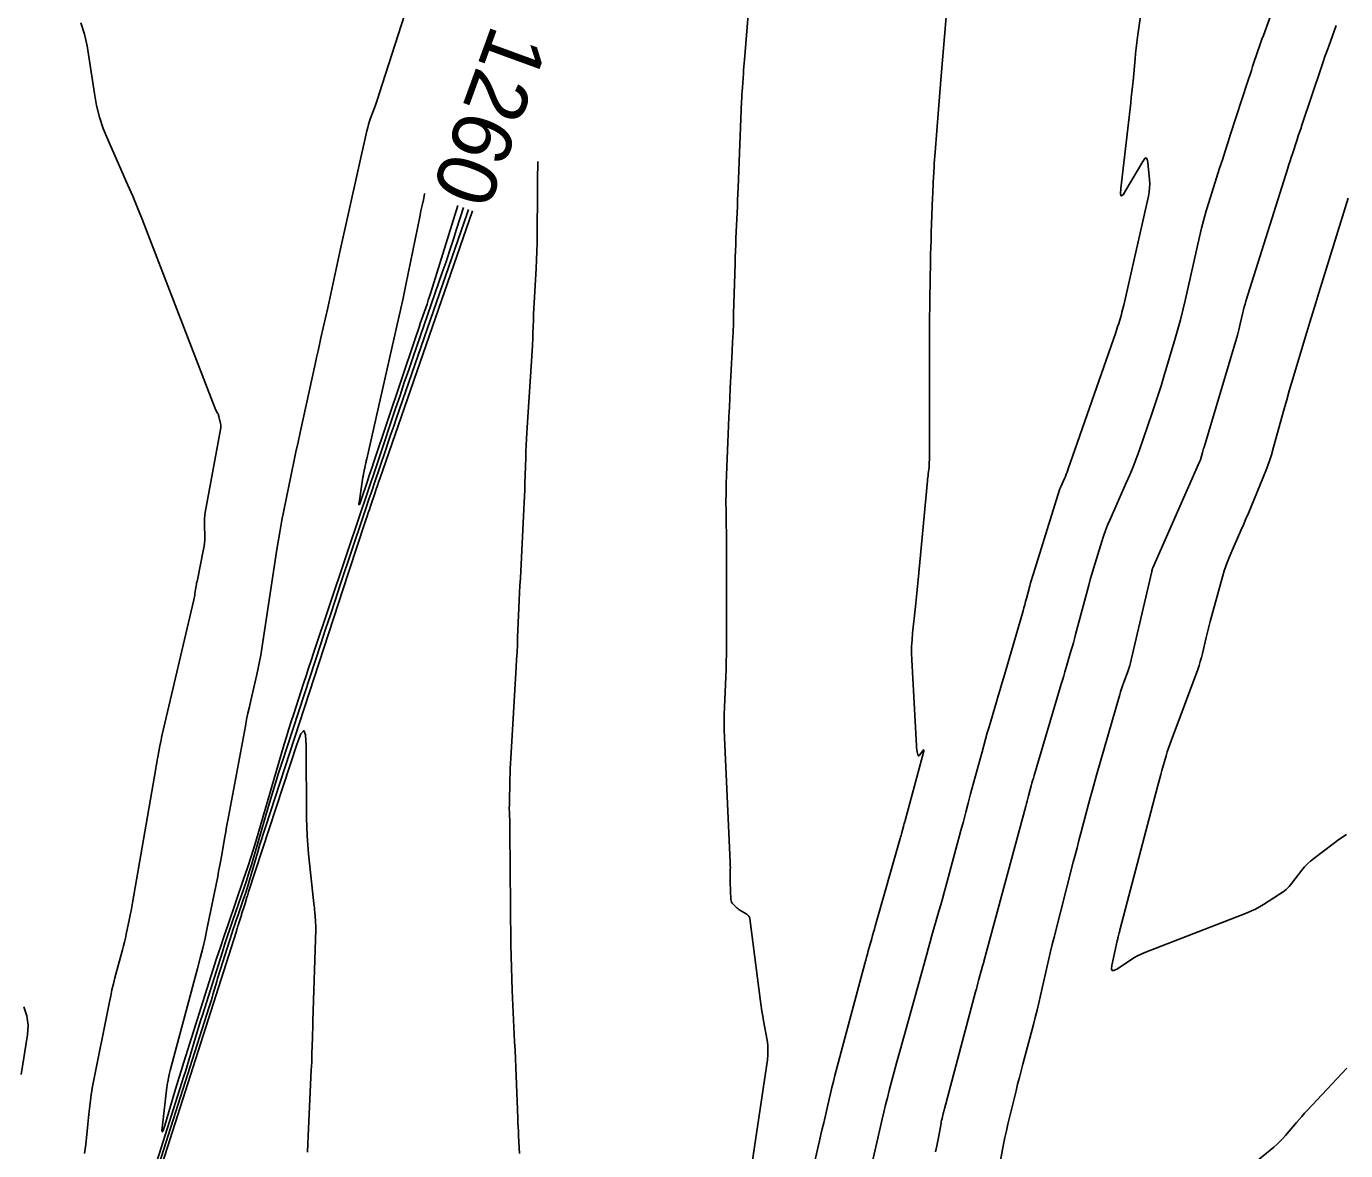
# Model space of a CAD drawing. Extents: x 658976 to 668726, y 639543 to 647196.
# Drawn here: x 661560 to 661691.9, y 641134.6 to 641247 of the extents above; entities that cross this region are included whole.
import ezdxf

# ---------------------------------------------------------------- set-up
doc = ezdxf.new("R2010")
doc.units = 0
for name, color, linetype in [('Ex_Contour Labels', 7, 'Continuous'), ('Ex_Major Contours', 7, 'Continuous'), ('Ex_Minor Contours', 7, 'Continuous')]:
    doc.layers.add(name, color=color, linetype=linetype)

msp = doc.modelspace()

# ---------------------------------------------------------------- linework, layer by layer
at = {"layer": 'Ex_Major Contours'}
for points in [[(661672.25, 641254.14), (661671.08, 641245.9), (661671, 641245.35), (661670.93, 641244.8), (661670.87, 641244.25), (661670.82, 641243.71), (661670.62, 641241.51), (661670.57, 641240.96), (661670.51, 641240.41), (661670.45, 641239.86), (661670.39, 641239.32), (661669.39, 641230.77), (661669.36, 641230.24), (661669.44, 641230.03), (661669.63, 641230.15), (661669.92, 641230.59), (661671.6, 641233.48), (661671.79, 641233.75), (661671.94, 641233.82), (661672.05, 641233.69), (661672.11, 641233.37), (661672.27, 641231.67), (661672.29, 641231.25), (661672.28, 641230.83), (661672.23, 641230.41), (661672.16, 641230), (661669.69, 641219.1), (661669.64, 641218.87), (661669.58, 641218.64), (661669.52, 641218.41), (661669.46, 641218.18), (661669.19, 641217.28), (661669.12, 641217.05), (661669.05, 641216.83), (661668.97, 641216.6), (661668.9, 641216.38), (661664.1, 641202.64), (661664.03, 641202.42), (661663.95, 641202.21), (661663.86, 641202), (661663.77, 641201.8), (661663.41, 641200.97), (661663.32, 641200.76), (661663.23, 641200.55), (661663.16, 641200.34), (661663.09, 641200.12), (661660.67, 641192.29), (661660.57, 641191.98), (661660.48, 641191.67), (661660.39, 641191.36), (661660.31, 641191.05), (661659.98, 641189.8), (661659.89, 641189.49), (661659.81, 641189.18), (661659.72, 641188.87), (661659.63, 641188.56), (661657.7, 641181.94), (661657.52, 641181.32), (661657.33, 641180.7), (661657.15, 641180.08), (661656.97, 641179.46), (661656.23, 641176.98), (661656.05, 641176.36), (661655.87, 641175.74), (661655.7, 641175.12), (661655.53, 641174.49), (661654.39, 641170.27), (661654.15, 641169.35), (661653.9, 641168.44), (661653.66, 641167.53), (661653.41, 641166.62), (661651.9, 641161.03), (661651.74, 641160.41), (661651.57, 641159.8), (661651.4, 641159.18), (661651.22, 641158.57), (661650.52, 641156.11), (661650.35, 641155.5), (661650.17, 641154.88), (661650, 641154.27), (661649.83, 641153.65), (661647.8, 641146.34), (661647.6, 641145.63), (661647.41, 641144.91), (661647.21, 641144.2), (661647.02, 641143.49), (661646.26, 641140.63), (661646.07, 641139.91), (661645.89, 641139.2), (661645.71, 641138.48), (661645.55, 641137.76), (661642.97, 641126.54)], [(661599.83, 641230.27), (661599.81, 641230.21), (661599.69, 641229.64), (661599.56, 641229.08), (661599.44, 641228.52), (661599.33, 641227.95), (661597.92, 641221.14), (661597.65, 641219.82), (661597.36, 641218.49), (661597.07, 641217.17), (661596.78, 641215.86), (661594.03, 641203.75), (661594, 641203.65), (661593.98, 641203.55), (661593.96, 641203.44), (661593.94, 641203.34), (661593.84, 641202.88), (661593.82, 641202.8), (661593.8, 641202.72), (661593.78, 641202.64), (661593.77, 641202.56), (661593.7, 641202.24), (661593.69, 641202.17), (661593.67, 641202.09), (661593.66, 641202.01), (661593.64, 641201.92), (661593.29, 641199.59), (661593.25, 641199.27), (661593.26, 641199.16), (661593.32, 641199.26), (661593.43, 641199.55), (661594.09, 641201.52), (661594.25, 641201.99), (661594.4, 641202.45), (661594.56, 641202.91), (661594.71, 641203.37), (661598.86, 641215.75), (661598.99, 641216.13), (661599.12, 641216.52), (661599.25, 641216.91), (661599.38, 641217.29), (661599.92, 641218.83), (661600.05, 641219.22), (661600.18, 641219.6), (661600.3, 641219.99), (661600.43, 641220.38), (661603.14, 641229.07)]]:
    msp.add_lwpolyline(points, dxfattribs=at)
at = {"layer": 'Ex_Minor Contours'}
for points in [[(661600.69, 641257.11), (661595.27, 641240.22), (661595.17, 641239.91), (661595.06, 641239.61), (661594.96, 641239.3), (661594.85, 641239), (661594.41, 641237.78), (661594.31, 641237.48), (661594.21, 641237.17), (661594.13, 641236.86), (661594.05, 641236.54), (661591.32, 641224.43), (661591.22, 641223.97), (661591.12, 641223.5), (661591.02, 641223.04), (661590.92, 641222.57), (661590.54, 641220.71), (661590.44, 641220.25), (661590.34, 641219.78), (661590.24, 641219.32), (661590.14, 641218.86), (661589.45, 641215.84), (661589.3, 641215.19), (661589.16, 641214.53), (661589.01, 641213.87), (661588.87, 641213.21), (661587.37, 641206.38), (661587.16, 641205.41), (661586.95, 641204.44), (661586.75, 641203.46), (661586.54, 641202.49), (661585.74, 641198.59), (661585.54, 641197.62), (661585.36, 641196.64), (661585.19, 641195.66), (661585.03, 641194.68), (661583.54, 641184.79), (661583.43, 641184.13), (661583.31, 641183.49), (661583.18, 641182.84), (661583.04, 641182.19), (661582.44, 641179.62), (661582.29, 641178.98), (661582.15, 641178.33), (661582.02, 641177.69), (661581.89, 641177.04), (661580.2, 641167.97), (661580.11, 641167.48), (661580.02, 641166.98), (661579.93, 641166.48), (661579.84, 641165.99), (661579.5, 641164), (661579.41, 641163.5), (661579.32, 641163), (661579.22, 641162.51), (661579.13, 641162.01), (661578.07, 641156.89), (661577.86, 641155.87), (661577.63, 641154.86), (661577.38, 641153.85), (661577.12, 641152.84), (661574.37, 641142.63), (661574.34, 641142.5), (661574.3, 641142.36), (661574.27, 641142.22), (661574.24, 641142.08), (661574.13, 641141.51), (661574.1, 641141.37), (661574.08, 641141.23), (661574.06, 641141.09), (661574.04, 641140.95), (661573.6, 641137.18), (661573.55, 641136.67), (661573.58, 641136.5), (661573.67, 641136.65), (661573.83, 641137.13), (661574.81, 641140.42), (661575.04, 641141.19), (661575.27, 641141.95), (661575.51, 641142.71), (661575.74, 641143.47), (661578.65, 641152.67), (661579.02, 641153.81), (661579.39, 641154.95), (661579.77, 641156.09), (661580.16, 641157.22), (661581.72, 641161.76), (661582.11, 641162.89), (661582.48, 641164.03), (661582.83, 641165.18), (661583.18, 641166.33), (661585.78, 641175.23), (661586.01, 641175.99), (661586.24, 641176.76), (661586.48, 641177.52), (661586.72, 641178.28), (661587.71, 641181.31), (661587.96, 641182.07), (661588.21, 641182.83), (661588.46, 641183.59), (661588.71, 641184.34), (661593.47, 641198.51), (661593.9, 641199.8), (661594.33, 641201.08), (661594.76, 641202.37), (661595.19, 641203.65), (661596.91, 641208.8), (661597.35, 641210.09), (661597.78, 641211.37), (661598.22, 641212.65), (661598.66, 641213.94), (661601.58, 641222.36), (661601.95, 641223.44), (661602.31, 641224.52), (661602.66, 641225.6), (661603, 641226.69), (661603.68, 641228.87)], [(661631.92, 641129.22), (661634.07, 641143.7), (661634.12, 641144.19), (661634.13, 641144.68), (661634.11, 641145.16), (661634.04, 641145.65), (661633.69, 641147.59), (661633.61, 641148.07), (661633.53, 641148.56), (661633.46, 641149.05), (661633.39, 641149.53), (661632.31, 641157.82), (661632.28, 641157.95), (661632.22, 641158.07), (661632.13, 641158.17), (661632.02, 641158.25), (661631.49, 641158.54), (661631.37, 641158.61), (661631.26, 641158.69), (661631.15, 641158.78), (661631.05, 641158.87), (661630.64, 641159.25), (661630.55, 641159.35), (661630.48, 641159.46), (661630.44, 641159.58), (661630.43, 641159.71), (661630.35, 641161.44), (661630.35, 641161.6), (661630.34, 641161.77), (661630.34, 641161.93), (661630.35, 641162.09), (661630.36, 641162.75), (661630.37, 641162.92), (661630.36, 641163.08), (661630.36, 641163.24), (661630.36, 641163.41), (661629.79, 641175.92), (661629.76, 641176.68), (661629.75, 641177.43), (661629.76, 641178.19), (661629.78, 641178.94), (661629.91, 641181.96), (661629.94, 641182.71), (661629.96, 641183.46), (661629.97, 641184.22), (661629.98, 641184.97), (661630, 641191.38), (661630, 641192.27), (661630, 641193.17), (661629.99, 641194.06), (661629.98, 641194.96), (661629.94, 641198.55), (661629.93, 641199.44), (661629.94, 641200.34), (661629.96, 641201.24), (661629.99, 641202.13), (661630.19, 641207.05), (661630.23, 641207.99), (661630.27, 641208.92), (661630.31, 641209.85), (661630.36, 641210.78), (661630.55, 641214.51), (661630.6, 641215.44), (661630.64, 641216.38), (661630.68, 641217.31), (661630.7, 641218.24), (661630.84, 641223.28), (661630.86, 641223.91), (661630.88, 641224.55), (661630.91, 641225.18), (661630.93, 641225.81), (661631.04, 641228.34), (661631.07, 641228.97), (661631.1, 641229.6), (661631.13, 641230.23), (661631.15, 641230.86), (661631.49, 641239.47), (661631.51, 641239.82), (661631.52, 641240.16), (661631.54, 641240.51), (661631.57, 641240.86), (661631.67, 641242.25), (661631.69, 641242.6), (661631.72, 641242.95), (661631.75, 641243.29), (661631.77, 641243.64), (661632.59, 641253.44)], [(661686.44, 641253.78), (661683.65, 641246.06), (661683.51, 641245.68), (661683.38, 641245.29), (661683.24, 641244.9), (661683.11, 641244.51), (661682.58, 641242.95), (661682.45, 641242.56), (661682.32, 641242.17), (661682.19, 641241.78), (661682.07, 641241.38), (661680.37, 641236.19), (661680.09, 641235.34), (661679.82, 641234.49), (661679.55, 641233.64), (661679.28, 641232.79), (661678.2, 641229.38), (661677.94, 641228.52), (661677.7, 641227.66), (661677.48, 641226.8), (661677.27, 641225.93), (661675.83, 641219.56), (661675.61, 641218.61), (661675.37, 641217.66), (661675.11, 641216.71), (661674.84, 641215.77), (661673.71, 641211.97), (661673.44, 641211.06), (661673.15, 641210.15), (661672.85, 641209.24), (661672.54, 641208.34), (661671.23, 641204.56), (661670.93, 641203.75), (661670.62, 641202.94), (661670.3, 641202.14), (661669.95, 641201.34), (661668.3, 641197.63), (661668.08, 641197.11), (661667.87, 641196.58), (661667.68, 641196.04), (661667.51, 641195.5), (661666.83, 641193.32), (661666.67, 641192.78), (661666.51, 641192.23), (661666.35, 641191.69), (661666.2, 641191.14), (661664.88, 641186.19), (661664.77, 641185.78), (661664.66, 641185.36), (661664.54, 641184.95), (661664.42, 641184.54), (661663.94, 641182.89), (661663.82, 641182.48), (661663.7, 641182.06), (661663.58, 641181.65), (661663.45, 641181.24), (661660.73, 641172.1), (661660.66, 641171.84), (661660.59, 641171.59), (661660.52, 641171.34), (661660.45, 641171.08), (661660.18, 641170.07), (661660.11, 641169.81), (661660.04, 641169.56), (661659.97, 641169.3), (661659.9, 641169.05), (661655.72, 641153.53), (661655.72, 641153.51), (661655.71, 641153.49), (661655.7, 641153.47), (661655.7, 641153.45), (661655.67, 641153.36), (661655.66, 641153.32), (661655.65, 641153.28), (661655.19, 641151.63), (661655.12, 641151.35), (661655.04, 641151.07), (661654.96, 641150.79), (661654.89, 641150.5), (661651.77, 641138.8), (661651.74, 641138.68), (661651.71, 641138.57), (661651.68, 641138.45), (661651.65, 641138.33), (661651.54, 641137.85), (661651.51, 641137.74), (661651.48, 641137.62), (661651.46, 641137.5), (661651.43, 641137.38), (661651.13, 641135.74), (661651.07, 641135.43), (661651.01, 641135.12), (661650.95, 641134.81), (661650.89, 641134.5)], [(661565.82, 641134.34), (661565.88, 641134.79), (661565.93, 641135.24), (661566.14, 641137.26), (661566.18, 641137.59), (661566.21, 641137.92), (661566.25, 641138.25), (661566.29, 641138.58), (661566.44, 641139.9), (661566.48, 641140.23), (661566.53, 641140.56), (661566.59, 641140.88), (661566.65, 641141.21), (661568.3, 641149.48), (661568.43, 641150.08), (661568.56, 641150.68), (661568.71, 641151.29), (661568.86, 641151.88), (661569.62, 641154.7), (661569.72, 641155.09), (661569.82, 641155.47), (661569.91, 641155.86), (661569.99, 641156.25), (661570.31, 641157.81), (661570.39, 641158.2), (661570.46, 641158.59), (661570.53, 641158.98), (661570.6, 641159.37), (661572.93, 641172.81), (661572.98, 641173.09), (661573.03, 641173.38), (661573.08, 641173.66), (661573.14, 641173.94), (661573.35, 641175.08), (661573.4, 641175.36), (661573.46, 641175.64), (661573.52, 641175.92), (661573.58, 641176.2), (661576.74, 641189.68), (661576.77, 641189.83), (661576.8, 641189.98), (661576.83, 641190.14), (661576.85, 641190.29), (661576.95, 641190.9), (661576.97, 641191.05), (661577, 641191.2), (661577.02, 641191.35), (661577.06, 641191.5), (661577.72, 641194.72), (661577.78, 641195.02), (661577.81, 641195.32), (661577.83, 641195.63), (661577.83, 641195.94), (661577.79, 641197.17), (661577.79, 641197.47), (661577.8, 641197.78), (661577.83, 641198.08), (661577.88, 641198.39), (661579.42, 641206.7), (661579.44, 641206.84), (661579.44, 641206.99), (661579.43, 641207.14), (661579.4, 641207.28), (661579.24, 641207.99), (661579.22, 641208.07), (661579.19, 641208.16), (661579.16, 641208.24), (661579.12, 641208.32), (661578.95, 641208.63), (661578.91, 641208.71), (661578.87, 641208.79), (661578.83, 641208.87), (661578.8, 641208.95), (661572.02, 641226.57), (661571.57, 641227.71), (661571.11, 641228.85), (661570.63, 641229.99), (661570.14, 641231.11), (661568.14, 641235.66), (661567.69, 641236.77), (661567.32, 641237.91), (661567.02, 641239.07), (661566.8, 641240.25), (661566.07, 641245.02), (661565.82, 641246.19), (661565.46, 641247.32)], [(661651.94, 641247.93), (661651.46, 641242.03), (661651.39, 641241.19), (661651.32, 641240.35), (661651.26, 641239.51), (661651.19, 641238.67), (661650.84, 641234.39), (661650.81, 641234.02), (661650.78, 641233.64), (661650.76, 641233.27), (661650.74, 641232.89), (661650.65, 641231.39), (661650.63, 641231.01), (661650.62, 641230.64), (661650.6, 641230.26), (661650.58, 641229.88), (661650.45, 641226.33), (661650.43, 641225.62), (661650.41, 641224.9), (661650.39, 641224.18), (661650.38, 641223.47), (661650.32, 641219.7), (661650.3, 641218.84), (661650.29, 641217.97), (661650.29, 641217.1), (661650.29, 641216.24), (661650.27, 641203.63), (661650.26, 641203.45), (661650.26, 641203.28), (661650.24, 641203.1), (661650.23, 641202.93), (661650.15, 641202.24), (661650.13, 641202.06), (661650.11, 641201.89), (661650.09, 641201.71), (661650.07, 641201.54), (661649.15, 641191.66), (661649.09, 641190.99), (661649.02, 641190.33), (661648.95, 641189.66), (661648.88, 641189), (661648.59, 641186.34), (661648.53, 641185.68), (661648.49, 641185.01), (661648.49, 641184.35), (661648.51, 641183.68), (661648.97, 641175.09), (661648.98, 641174.97), (661648.99, 641174.86), (661649, 641174.75), (661649.02, 641174.63), (661649.11, 641174.18), (661649.14, 641174.1), (661649.17, 641174.06), (661649.22, 641174.07), (661649.29, 641174.14), (661649.61, 641174.58), (661649.68, 641174.66), (661649.71, 641174.67), (661649.72, 641174.64), (661649.7, 641174.54), (661647.85, 641167.63), (661647.8, 641167.48), (661647.76, 641167.33), (661647.72, 641167.17), (661647.68, 641167.02), (661647.52, 641166.41), (661647.47, 641166.25), (661647.43, 641166.1), (661647.39, 641165.95), (661647.35, 641165.8), (661644.86, 641157.06), (661644.77, 641156.75), (661644.68, 641156.44), (661644.59, 641156.13), (661644.51, 641155.82), (661644.16, 641154.58), (661644.08, 641154.27), (661643.99, 641153.96), (661643.91, 641153.65), (661643.82, 641153.34), (661640.83, 641142.12), (661640.67, 641141.53), (661640.53, 641140.94), (661640.38, 641140.35), (661640.24, 641139.76), (661639.7, 641137.4), (661639.56, 641136.81), (661639.43, 641136.22), (661639.29, 641135.62), (661639.16, 641135.03), (661637.03, 641125.67)], [(661655.44, 641123.22), (661657.69, 641135.27), (661657.82, 641135.94), (661657.96, 641136.61), (661658.11, 641137.28), (661658.27, 641137.95), (661658.93, 641140.61), (661659.09, 641141.27), (661659.26, 641141.94), (661659.43, 641142.6), (661659.61, 641143.26), (661660.66, 641147.22), (661660.85, 641147.94), (661661.03, 641148.67), (661661.2, 641149.4), (661661.37, 641150.13), (661662.03, 641153.05), (661662.19, 641153.78), (661662.37, 641154.51), (661662.55, 641155.23), (661662.73, 641155.96), (661664.65, 641163.44), (661664.84, 641164.16), (661665.03, 641164.89), (661665.22, 641165.62), (661665.41, 641166.34), (661666.17, 641169.25), (661666.36, 641169.97), (661666.56, 641170.69), (661666.76, 641171.42), (661666.96, 641172.14), (661669.29, 641180.19), (661669.37, 641180.48), (661669.47, 641180.77), (661669.57, 641181.06), (661669.67, 641181.35), (661670.1, 641182.5), (661670.2, 641182.79), (661670.3, 641183.09), (661670.38, 641183.38), (661670.45, 641183.68), (661672.49, 641192.49), (661672.5, 641192.52), (661672.5, 641192.55), (661672.51, 641192.58), (661672.52, 641192.61), (661672.55, 641192.73), (661672.56, 641192.76), (661672.57, 641192.79), (661672.58, 641192.82), (661672.59, 641192.85), (661677.28, 641203.44), (661677.29, 641203.46), (661677.3, 641203.48), (661677.31, 641203.5), (661677.31, 641203.51), (661677.34, 641203.59), (661677.35, 641203.6), (661677.36, 641203.62), (661677.36, 641203.64), (661677.37, 641203.66), (661677.57, 641204.4), (661677.61, 641204.53), (661677.65, 641204.66), (661677.68, 641204.79), (661677.72, 641204.92), (661681.05, 641216.1), (661681.13, 641216.38), (661681.2, 641216.66), (661681.27, 641216.95), (661681.34, 641217.23), (661681.6, 641218.37), (661681.67, 641218.66), (661681.74, 641218.94), (661681.82, 641219.22), (661681.9, 641219.5), (661686.1, 641232.81), (661686.21, 641233.16), (661686.33, 641233.52), (661686.44, 641233.88), (661686.56, 641234.24), (661687.02, 641235.67), (661687.14, 641236.03), (661687.26, 641236.39), (661687.38, 641236.74), (661687.5, 641237.1), (661689.46, 641242.92), (661689.64, 641243.44), (661689.81, 641243.96), (661690, 641244.47), (661690.18, 641244.98), (661690.92, 641247.04)], [(661609.31, 641134.33), (661609.21, 641136.1), (661609.18, 641136.54), (661609.16, 641136.99), (661609.14, 641137.43), (661609.12, 641137.87), (661608.95, 641142.09), (661608.92, 641142.94), (661608.88, 641143.79), (661608.85, 641144.64), (661608.81, 641145.49), (661608.57, 641150.64), (661608.52, 641151.79), (661608.48, 641152.93), (661608.46, 641154.07), (661608.44, 641155.21), (661608.34, 641166.61), (661608.34, 641166.82), (661608.33, 641167.03), (661608.33, 641167.24), (661608.32, 641167.45), (661608.28, 641168.29), (661608.28, 641168.5), (661608.27, 641168.71), (661608.27, 641168.92), (661608.28, 641169.13), (661608.34, 641171.79), (661608.36, 641172.3), (661608.37, 641172.81), (661608.4, 641173.32), (661608.43, 641173.83), (661608.96, 641182.95), (661609.01, 641183.69), (661609.05, 641184.43), (661609.08, 641185.17), (661609.11, 641185.91), (661609.24, 641188.88), (661609.27, 641189.62), (661609.31, 641190.36), (661609.34, 641191.1), (661609.38, 641191.84), (661609.74, 641198.74), (661609.77, 641199.38), (661609.8, 641200.01), (661609.82, 641200.65), (661609.84, 641201.29), (661609.92, 641203.84), (661609.94, 641204.47), (661609.97, 641205.11), (661610, 641205.75), (661610.04, 641206.39), (661610.59, 641215.04), (661610.61, 641215.31), (661610.62, 641215.57), (661610.63, 641215.83), (661610.64, 641216.1), (661610.67, 641217.15), (661610.68, 641217.41), (661610.69, 641217.68), (661610.7, 641217.94), (661610.71, 641218.2), (661610.95, 641222.78), (661610.99, 641223.63), (661611.02, 641224.48), (661611.05, 641225.33), (661611.06, 641226.18), (661611.1, 641230.41), (661611.1, 641231.25), (661611.11, 641232.09), (661611.12, 641232.94), (661611.13, 641233.47)], [(661691.95, 641166.21), (661691.5, 641165.91), (661691.06, 641165.6), (661690.62, 641165.27), (661688.68, 641163.82), (661688.36, 641163.56), (661688.05, 641163.28), (661687.77, 641162.98), (661687.51, 641162.66), (661686.49, 641161.34), (661686.23, 641161.02), (661685.94, 641160.73), (661685.62, 641160.47), (661685.28, 641160.24), (661683.66, 641159.22), (661683.27, 641158.99), (661682.87, 641158.77), (661682.46, 641158.58), (661682.04, 641158.4), (661671.81, 641154.41), (661671.43, 641154.25), (661671.07, 641154.08), (661670.71, 641153.88), (661670.37, 641153.67), (661669, 641152.77), (661668.71, 641152.62), (661668.53, 641152.63), (661668.46, 641152.8), (661668.49, 641153.12), (661669.05, 641155.6), (661669.07, 641155.7), (661669.1, 641155.8), (661669.12, 641155.9), (661669.15, 641155.99), (661669.25, 641156.39), (661669.27, 641156.49), (661669.3, 641156.58), (661669.32, 641156.68), (661669.35, 641156.78), (661673.09, 641171.1), (661673.19, 641171.47), (661673.29, 641171.85), (661673.4, 641172.22), (661673.5, 641172.6), (661673.93, 641174.09), (661674.05, 641174.47), (661674.16, 641174.84), (661674.29, 641175.2), (661674.42, 641175.57), (661677.09, 641182.71), (661677.23, 641183.1), (661677.35, 641183.49), (661677.47, 641183.89), (661677.57, 641184.29), (661677.94, 641185.9), (661678.03, 641186.31), (661678.13, 641186.71), (661678.24, 641187.11), (661678.34, 641187.51), (661679.56, 641191.95), (661679.73, 641192.55), (661679.93, 641193.14), (661680.15, 641193.73), (661680.39, 641194.31), (661681.41, 641196.6), (661681.66, 641197.17), (661681.91, 641197.75), (661682.15, 641198.32), (661682.39, 641198.9), (661683.68, 641202), (661683.96, 641202.72), (661684.22, 641203.44), (661684.46, 641204.17), (661684.68, 641204.91), (661685.74, 641208.76), (661685.99, 641209.65), (661686.24, 641210.54), (661686.5, 641211.42), (661686.76, 641212.31), (661688, 641216.42), (661688.3, 641217.4), (661688.59, 641218.38), (661688.89, 641219.35), (661689.2, 641220.33), (661692.12, 641229.81)], [(661604.6, 641228.53), (661595.33, 641201.76), (661595.21, 641201.42), (661595.09, 641201.08), (661594.98, 641200.73), (661594.86, 641200.39), (661594.41, 641199.03), (661594.29, 641198.69), (661594.18, 641198.35), (661594.07, 641198.01), (661593.95, 641197.67), (661592.96, 641194.72), (661592.76, 641194.12), (661592.56, 641193.51), (661592.36, 641192.91), (661592.16, 641192.3), (661583.9, 641166.96), (661583.7, 641166.34), (661583.51, 641165.72), (661583.32, 641165.1), (661583.13, 641164.48), (661582.31, 641161.65), (661582.17, 641161.2), (661582.03, 641160.76), (661581.89, 641160.31), (661581.74, 641159.87), (661581.13, 641158.1), (661580.98, 641157.66), (661580.83, 641157.21), (661580.68, 641156.77), (661580.54, 641156.32), (661579.42, 641152.77), (661579.32, 641152.45), (661579.22, 641152.14), (661579.12, 641151.82), (661579.03, 641151.51), (661578.65, 641150.24), (661578.56, 641149.93), (661578.46, 641149.61), (661578.36, 641149.3), (661578.27, 641148.98), (661571.8, 641128.71)], [(661604.21, 641228.68), (661604.06, 641228.26), (661597, 641207.85), (661596.72, 641207.03), (661596.44, 641206.22), (661596.16, 641205.41), (661595.89, 641204.6), (661594.8, 641201.34), (661594.53, 641200.53), (661594.25, 641199.72), (661593.98, 641198.9), (661593.71, 641198.09), (661591.35, 641191.06), (661590.87, 641189.61), (661590.39, 641188.17), (661589.91, 641186.72), (661589.44, 641185.28), (661585.58, 641173.44), (661585.22, 641172.34), (661584.88, 641171.24), (661584.54, 641170.13), (661584.22, 641169.03), (661582.74, 641163.99), (661582.5, 641163.19), (661582.25, 641162.4), (661582, 641161.6), (661581.73, 641160.81), (661580.64, 641157.66), (661580.37, 641156.87), (661580.11, 641156.08), (661579.85, 641155.29), (661579.6, 641154.49), (661577.59, 641148.17), (661577.42, 641147.61), (661577.25, 641147.04), (661577.07, 641146.48), (661576.91, 641145.92), (661576.24, 641143.67), (661576.07, 641143.11), (661575.9, 641142.54), (661575.72, 641141.98), (661575.54, 641141.42), (661572.83, 641132.9)], [(661588.1, 641134.47), (661588.12, 641135.29), (661588.16, 641136.11), (661588.48, 641142.66), (661588.5, 641143.07), (661588.52, 641143.48), (661588.54, 641143.89), (661588.55, 641144.3), (661588.6, 641145.94), (661588.61, 641146.35), (661588.63, 641146.76), (661588.64, 641147.17), (661588.65, 641147.58), (661588.92, 641156.71), (661588.92, 641156.93), (661588.92, 641157.15), (661588.91, 641157.36), (661588.9, 641157.58), (661588.83, 641158.45), (661588.81, 641158.66), (661588.79, 641158.88), (661588.77, 641159.1), (661588.75, 641159.31), (661588.21, 641164.27), (661588.13, 641165.17), (661588.07, 641166.07), (661588.03, 641166.97), (661588.01, 641167.87), (661587.97, 641175.06), (661587.9, 641176.19), (661587.72, 641176.6), (661587.43, 641176.27), (661587.02, 641175.21), (661582.22, 641160.48), (661582.18, 641160.34), (661582.13, 641160.21), (661582.09, 641160.07), (661582.05, 641159.94), (661581.87, 641159.32), (661581.84, 641159.22), (661581.81, 641159.12), (661581.78, 641159.02), (661581.75, 641158.92), (661581.61, 641158.54), (661581.58, 641158.44), (661581.55, 641158.34), (661581.52, 641158.25), (661581.49, 641158.15), (661581.24, 641157.37), (661581.22, 641157.3), (661581.2, 641157.23), (661581.18, 641157.16), (661581.15, 641157.09), (661581.07, 641156.82), (661581.05, 641156.75), (661581.03, 641156.68), (661581.01, 641156.61), (661580.99, 641156.54), (661570.78, 641124.53)], [(661559.47, 641142.23), (661560.1, 641146.2), (661560.17, 641147.17), (661560.05, 641148.1), (661559.74, 641148.99)], [(661692, 641142.88), (661691.45, 641142.29), (661688.05, 641138.66), (661687.77, 641138.36), (661687.49, 641138.05), (661687.22, 641137.73), (661686.95, 641137.42), (661685.87, 641136.14), (661685.6, 641135.83), (661685.31, 641135.53), (661685.01, 641135.25), (661684.69, 641134.98), (661678.64, 641130.01)]]:
    msp.add_lwpolyline(points, dxfattribs=at)

# ---------------------------------------------------------------- texts
at = {"layer": 'Ex_Contour Labels'}
msp.add_text('1260', height=6, rotation=249.9948, dxfattribs=at).set_placement((661606.59, 641247.32))

doc.saveas('drawing.dxf')
